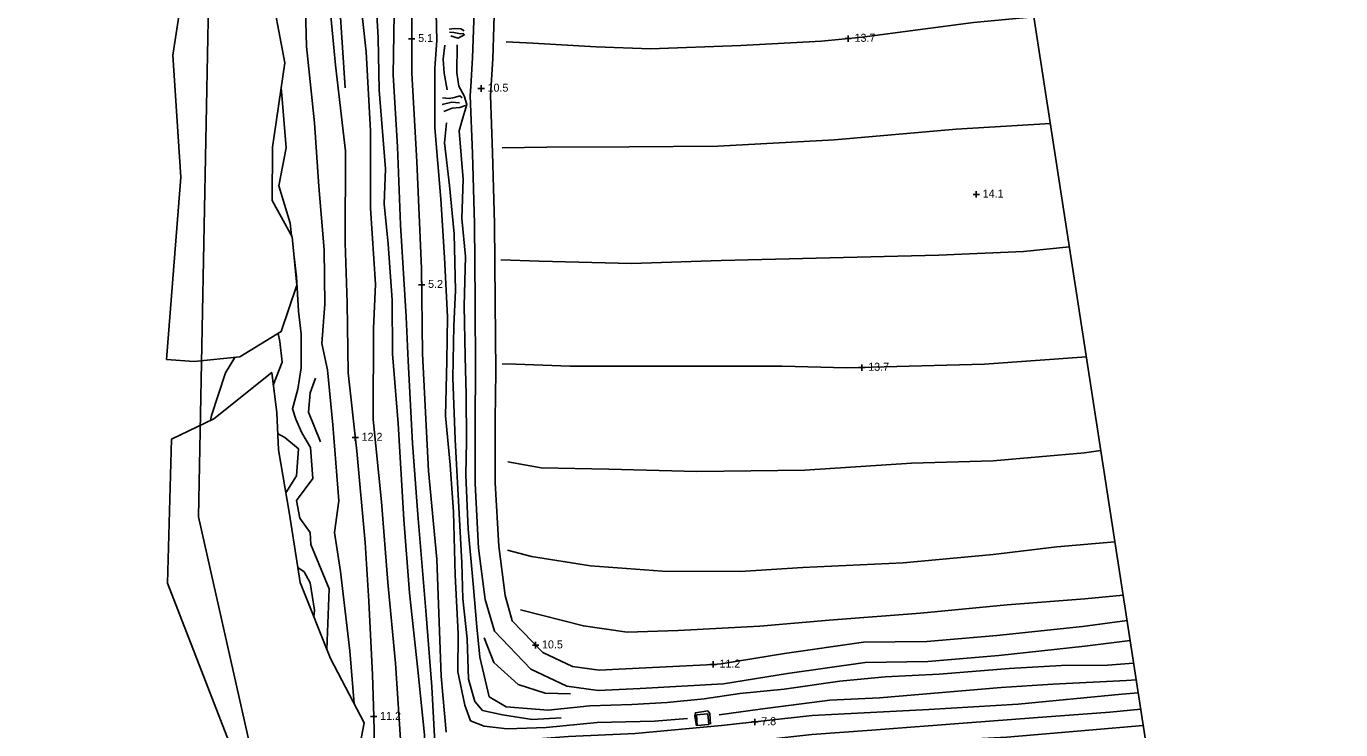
# Model space of a CAD drawing. Extents: x 2316231 to 2323598, y 363169 to 371906.
# Drawn here: x 2321107 to 2321928, y 367333 to 367772 of the extents above; entities that cross this region are included whole.
import ezdxf

# ---------------------------------------------------------------- set-up
doc = ezdxf.new("R2010")
doc.units = 0
for name, color, linetype in [('RD_DTM_BkLn1', 7, 'Continuous'), ('RD_DTM_Holes', 7, 'Continuous'), ('RD_DTM_TinHull', 7, 'Continuous'), ('RD_DTM_Void', 7, 'Continuous'), ('RD_EX_H2O', 7, 'Continuous'), ('RD_EX_Road', 7, 'Continuous')]:
    doc.layers.add(name, color=color, linetype=linetype)

msp = doc.modelspace()

# ---------------------------------------------------------------- linework, layer by layer
at = {"layer": 'RD_DTM_BkLn1'}
for points in [[(2321291.556, 368211.321), (2321295.001, 368190.387), (2321298.08, 368166.803), (2321301.743, 368125.311), (2321305.469, 368082.359), (2321306.836, 368033.666), (2321306.702, 368002.425), (2321307.621, 367978.771), (2321309.118, 367958.662), (2321310.087, 367912.89), (2321311.539, 367868.753), (2321315.416, 367819.072), (2321315.07, 367794.132), (2321319.37, 367756.054), (2321322.027, 367706.795), (2321322.055, 367658.395), (2321325.126, 367611.033), (2321323.802, 367583.298), (2321323.769, 367526.402), (2321328.977, 367475.147), (2321332.861, 367424.707), (2321337.695, 367374.238), (2321340.813, 367326.721), (2321341.673, 367288.712)], [(2321323.848, 368178.354), (2321329.394, 368134.038), (2321333.82, 368091.189), (2321336.523, 368053.927), (2321337.729, 368006.137), (2321339.028, 367970.354), (2321339.901, 367946.949), (2321338.401, 367905.143), (2321338.559, 367856.742), (2321336.201, 367820.434), (2321336.689, 367779.863), (2321336.124, 367741.67), (2321338.889, 367696.778), (2321340.671, 367647.964), (2321344.229, 367590.513), (2321345.519, 367563.202), (2321348.173, 367511.499), (2321351.642, 367467.184), (2321356.657, 367407.103), (2321360.332, 367359.488), (2321362.527, 367316.908)], [(2321259.144, 368129.166), (2321263.416, 368100.568), (2321268.448, 368072.192), (2321272.368, 368019.699), (2321273.45, 367993.54), (2321273.468, 367967.981), (2321272.707, 367951.314), (2321273.78, 367931.729), (2321274.21, 367887.23), (2321276.344, 367858.183), (2321280.683, 367806.494), (2321282.119, 367759.355), (2321287.064, 367711.792), (2321289.823, 367671.954), (2321293.058, 367632.446), (2321293.527, 367598.603), (2321291.556, 367573.993), (2321295.08, 367557.574), (2321298.476, 367523.214), (2321302.318, 367475.658), (2321299.498, 367455.835), (2321303.343, 367431.452), (2321309.119, 367381.926), (2321311.835, 367348.854)], [(2321296.973, 367943.164), (2321297.8, 367891.448), (2321301.079, 367812.439), (2321306.211, 367733.573)], [(2321324.018, 367340.884), (2321323.284, 367367.095), (2321320.999, 367412.97), (2321318.613, 367449.625), (2321313.402, 367506.623), (2321308.015, 367555.695), (2321307.438, 367599.364), (2321306.16, 367636.808), (2321306.457, 367694.13), (2321300.17, 367747.788), (2321294.617, 367807.101)], [(2321362.509, 367798.164), (2321363.504, 367763.154), (2321362.205, 367745.802), (2321362.227, 367708.722), (2321365.919, 367664.049), (2321368.33, 367627.608), (2321370.181, 367590.659), (2321369.724, 367563.062), (2321368.766, 367528.846), (2321371.721, 367498.156), (2321373.817, 367468.776), (2321374.916, 367429.162), (2321376.864, 367392.723), (2321376.536, 367368.934), (2321380.96, 367348.143), (2321384.558, 367338.381), (2321392.928, 367334.986), (2321407.453, 367333.24)], [(2321325.756, 367783.047), (2321326.872, 367764.755), (2321327.335, 367732.122), (2321331.382, 367683.033), (2321330.602, 367661.134), (2321332.959, 367635.929), (2321335.558, 367601.147), (2321335.671, 367567.436), (2321339.382, 367523.998), (2321342.772, 367463.961), (2321346.41, 367418.126), (2321351.625, 367370.075), (2321355.65, 367329.59), (2321356.833, 367292.277), (2321358.89, 367254.128), (2321360.361, 367211.012)], [(2321406.786, 367762.381), (2321423.381, 367761.454), (2321462.976, 367759.243), (2321496.869, 367757.943), (2321553.314, 367760.001), (2321603.808, 367762.852), (2321629.095, 367765.15), (2321698.646, 367774.31), (2321736.399, 367777.877)], [(2321371.234, 367770.288), (2321374.416, 367770.602), (2321378.403, 367770.532), (2321380.602, 367769.178)], [(2321371.342, 367768.425), (2321374.047, 367768.219), (2321378.147, 367767.377), (2321380.331, 367767.471)], [(2321372.207, 367766.058), (2321374.623, 367765.249), (2321376.861, 367764.608), (2321380.98, 367766.85)], [(2321368.507, 367760.289), (2321367.376, 367751.575), (2321367.978, 367742.791), (2321369.982, 367732.325)], [(2321376.161, 367760.518), (2321375.858, 367742.982), (2321377.21, 367734.668), (2321380.568, 367728.514), (2321382.246, 367723.212), (2321379.635, 367714.969), (2321377.368, 367706.759), (2321379.957, 367676.391), (2321378.961, 367651.906), (2321381.327, 367628.244), (2321380.484, 367597.434), (2321381.131, 367565.772), (2321381.716, 367541.883), (2321381.928, 367512.917), (2321381.496, 367491.716), (2321382.927, 367458.044), (2321386.063, 367423.912), (2321388.422, 367396.951), (2321390.234, 367377.944), (2321396.107, 367353.276), (2321406.762, 367347.08), (2321432.95, 367344.994), (2321458.986, 367347.62), (2321485.31, 367348.57), (2321507.328, 367349.76), (2321530.372, 367351.952), (2321552.7, 367355.406), (2321580.362, 367358.069), (2321615.205, 367363.029), (2321643.391, 367365.761), (2321677.301, 367367.403), (2321720.928, 367370.947), (2321753.64, 367372.763), (2321782.333, 367373.047), (2321798.692, 367374.245)], [(2321272.722, 367641.237), (2321271.772, 367648.992), (2321264.753, 367672.373), (2321269.257, 367696.042), (2321266.472, 367731.478), (2321266.154, 367733.618)], [(2321366.796, 367723.16), (2321372.856, 367724.572), (2321375.158, 367724.547), (2321377.612, 367724.236)], [(2321366.927, 367727.276), (2321371.102, 367726.991), (2321374.38, 367727.506), (2321377.827, 367728.578), (2321379.28, 367727.383)], [(2321367.72, 367718.835), (2321373, 367720.822), (2321377.856, 367721.351), (2321381.245, 367722.589)], [(2321369.4, 367711.706), (2321368.26, 367699.325), (2321371.32, 367672.514), (2321374.326, 367642.441), (2321375.116, 367606.957), (2321374.016, 367584.905), (2321373.412, 367552.527), (2321374.838, 367513.884), (2321377.035, 367475.414), (2321379.09, 367436.874), (2321379.755, 367414.515), (2321382.315, 367389.499), (2321383.285, 367364.338), (2321387.096, 367350.433), (2321391.893, 367344.793), (2321404.502, 367341.979), (2321422.996, 367339.107), (2321441.085, 367340.189)], [(2321404.218, 367696.102), (2321432.14, 367696.45), (2321483.414, 367696.77), (2321538.901, 367697.196), (2321611.886, 367701.127), (2321687.854, 367707.842), (2321746.664, 367711.361)], [(2321403.326, 367626.111), (2321427.421, 367625.449), (2321485.056, 367623.952), (2321541.026, 367625.763), (2321600.387, 367627.306), (2321677.062, 367629.021), (2321729.937, 367631.336), (2321758.557, 367634.303)], [(2321294.757, 367382.852), (2321296.138, 367420.72), (2321284.824, 367448.456), (2321284.286, 367455.876), (2321277.799, 367464.765), (2321275.752, 367475.848), (2321285.906, 367489.672), (2321284.594, 367508.961), (2321279.094, 367518.106), (2321275.466, 367526.765), (2321273.189, 367533.222), (2321276.665, 367545.352), (2321278.712, 367558.736), (2321278.622, 367580.072), (2321276.971, 367594.047), (2321275.873, 367615.507), (2321274.344, 367627.995)], [(2321261.282, 367547.974), (2321266.736, 367562.188), (2321265.293, 367575.284), (2321264.3, 367580.211)], [(2321237.271, 367565.251), (2321231.527, 367555.545), (2321222.771, 367528.969), (2321222.101, 367525.922)], [(2321404.325, 367561.164), (2321412.868, 367560.996), (2321446.583, 367559.756), (2321517.126, 367559.869), (2321579.088, 367559.723), (2321619.342, 367558.636), (2321705.596, 367560.971), (2321769.169, 367565.539)], [(2321287.669, 367552.253), (2321284.234, 367543.16), (2321283.239, 367531.087), (2321290.773, 367512.509)], [(2321269.146, 367480.568), (2321275.829, 367491.225), (2321276.983, 367508.198), (2321268.398, 367515.19), (2321263.988, 367517.677)], [(2321407.839, 367500.083), (2321428.618, 367496.296), (2321470.808, 367495.446), (2321525.904, 367494.046), (2321593.33, 367494.842), (2321659.91, 367499.143), (2321710.989, 367500.686), (2321767.962, 367505.695), (2321778.197, 367507.044)], [(2321407.626, 367444.884), (2321422.542, 367440.847), (2321459.458, 367435.115), (2321504.339, 367431.722), (2321552.845, 367431.536), (2321592.064, 367434.013), (2321654.827, 367436.972), (2321710.911, 367442.247), (2321750.736, 367446.964), (2321786.995, 367450.033)], [(2321286.694, 367403.07), (2321287.065, 367407.293), (2321284.33, 367424.55), (2321280.583, 367431.252), (2321276.633, 367433.945)], [(2321415.716, 367407.686), (2321454.981, 367397.55), (2321482.38, 367393.737), (2321514.21, 367394.667), (2321565.213, 367397.445), (2321608.426, 367401.181), (2321665.632, 367405.465), (2321719.628, 367410.812), (2321768.157, 367414.517), (2321792.139, 367416.706)], [(2321393.093, 367390.018), (2321398.96, 367374.63), (2321414.33, 367360.978), (2321431.1, 367355.565), (2321446.963, 367355.2)], [(2321539.753, 367342.119), (2321565.41, 367345.578), (2321608.978, 367351.187), (2321639.898, 367352.729), (2321715.9, 367359.182), (2321748.187, 367361.273), (2321794.143, 367363.415), (2321800.287, 367363.908)], [(2321383.243, 367297.551), (2321386.5, 367309.013), (2321395.766, 367314.976), (2321434.231, 367320.424), (2321475.646, 367323.151), (2321511.83, 367324.08), (2321529.119, 367324.075), (2321562.377, 367325.792), (2321597.747, 367329.681), (2321635.223, 367332.441), (2321694.923, 367337.008), (2321736.08, 367340.151), (2321783.86, 367343.789), (2321803.103, 367345.663)], [(2321534.458, 367336.206), (2321534.045, 367342.794), (2321532.69, 367344.451), (2321524.935, 367343.321), (2321524.568, 367341.413), (2321525.357, 367336.271), (2321525.54, 367335.178)], [(2321328.403, 367278.384), (2321324.798, 367313.014), (2321324.018, 367340.884)], [(2321407.453, 367333.24), (2321431.819, 367334.143), (2321463.577, 367337.187), (2321499.322, 367338.071), (2321520.058, 367339.744)], [(2321415.257, 367297.46), (2321430.604, 367306.835), (2321453.602, 367309.277), (2321487.438, 367310.338), (2321506.208, 367308.082), (2321516.399, 367305.792), (2321525.885, 367304.622), (2321530.952, 367310.691), (2321539.181, 367313.918), (2321563.501, 367315.142), (2321593.054, 367316.252), (2321642.292, 367321.567), (2321684.276, 367326.295), (2321719.575, 367328.025), (2321770.707, 367332.534), (2321804.686, 367335.402)]]:
    msp.add_lwpolyline(points, dxfattribs=at)
at = {"layer": 'RD_DTM_Holes'}
for points in [[(2321194.626, 367563.982), (2321211.931, 367562.731), (2321240.449, 367565.568), (2321266.278, 367581.425), (2321276.069, 367610.309), (2321273.123, 367640.512), (2321260.57, 367663.201), (2321260.823, 367696.519), (2321268.403, 367749.265), (2321258.641, 367801.152), (2321254.344, 367804.974), (2321247.579, 367829.207), (2321239.086, 367854.281), (2321227.889, 367865.18), (2321214.697, 367859.513), (2321198.6, 367753.989), (2321203.438, 367677.795), (2321194.626, 367563.982)], [(2321305.88, 367273.604), (2321317.984, 367337.094), (2321297.001, 367377.227), (2321278.065, 367424.705), (2321271.443, 367467.424), (2321264.449, 367507.44), (2321263.408, 367530.561), (2321260.327, 367555.794), (2321224.183, 367526.92), (2321197.743, 367514.235), (2321195.168, 367424.201), (2321257.373, 367263.844), (2321272.724, 367127.144), (2321274.192, 366988.754), (2321266.646, 366868.055), (2321260.533, 366796.556)]]:
    msp.add_lwpolyline(points, dxfattribs=at)
at = {"layer": 'RD_DTM_TinHull'}
for points in [[(2322749.057, 368805.183), (2322437.788, 368637.943), (2322185.484, 368501.144), (2321988.712, 368397.613), (2321906.574, 368261.806), (2321814.258, 368125.896), (2321753.197, 367969.571), (2321734.081, 367792.897), (2321812.341, 367285.803), (2321826.603, 366879.552), (2321787.983, 366568.052), (2321665.825, 366287.064), (2321428.475, 366067.062), (2321222.139, 365846.682), (2320971.939, 365770.635), (2320807.161, 365571.8), (2320809.363, 365353.877), (2320991.706, 364942.038)], [(2318009.783, 367630.234), (2318999.407, 367049.655), (2319281.252, 367000.442), (2319521.217, 366961.394), (2320716.689, 366226.888), (2320934.852, 366280.749), (2321141.465, 366502.562), (2321263.978, 366719.924), (2321282.537, 366948.249), (2321279.947, 367175.232), (2321214.652, 367465.641), (2321221.515, 367818.629), (2321207.427, 368150.673), (2321267.86, 368369.229), (2321400.963, 368599.408), (2321534.916, 368777.939)]]:
    msp.add_lwpolyline(points, dxfattribs=at)
at = {"layer": 'RD_DTM_Void'}
for p, q in [((2321345.775, 367764.221), (2321349.775, 367764.221)), ((2321347.775, 367762.221), (2321347.775, 367766.221)), ((2321618.349, 367764.355), (2321622.349, 367764.355)), ((2321620.349, 367762.355), (2321620.349, 367766.355)), ((2321389.132, 367733.199), (2321393.132, 367733.199)), ((2321391.132, 367731.199), (2321391.132, 367735.199)), ((2321698.397, 367667.057), (2321702.397, 367667.057)), ((2321700.397, 367665.057), (2321700.397, 367669.057)), ((2321351.982, 367610.638), (2321355.982, 367610.638)), ((2321353.982, 367608.638), (2321353.982, 367612.638)), ((2321626.889, 367558.894), (2321630.889, 367558.894)), ((2321628.889, 367556.894), (2321628.889, 367560.894)), ((2321312.465, 367513.161), (2321312.465, 367517.161)), ((2321310.465, 367515.161), (2321314.465, 367515.161)), ((2321423.148, 367385.515), (2321427.148, 367385.515)), ((2321425.148, 367383.515), (2321425.148, 367387.515)), ((2321534.008, 367373.538), (2321538.008, 367373.538)), ((2321536.008, 367371.538), (2321536.008, 367375.538)), ((2321322.018, 367340.884), (2321326.018, 367340.884)), ((2321324.018, 367338.884), (2321324.018, 367342.884)), ((2321560.075, 367337.551), (2321564.075, 367337.551)), ((2321562.075, 367335.551), (2321562.075, 367339.551))]:
    msp.add_line(p, q, dxfattribs=at)
at = {"layer": 'RD_EX_H2O'}
for points in [[(2321369.329, 367331.29), (2321366.09, 367366.171), (2321363.488, 367439.267), (2321358.267, 367494.497), (2321354.538, 367567.493), (2321353.85, 367620.821), (2321350.939, 367687.536), (2321347.746, 367742.694), (2321347.799, 367782.539), (2321347.874, 367844.466), (2321349.179, 367907.798), (2321351.639, 367957.667), (2321344.793, 367998.573), (2321347.089, 368028.366), (2321348.65, 368062.186), (2321346.173, 368103.66), (2321341.01, 368148.317), (2321343.787, 368191.312)], [(2321801.546, 367355.747), (2321791.305, 367354.864), (2321726.612, 367348.618), (2321670.729, 367345.347), (2321597.982, 367341.509), (2321541.334, 367335.264), (2321487.317, 367330.345), (2321445.669, 367328.545), (2321421.333, 367326.586), (2321395.38, 367326.144), (2321370.092, 367323.418)]]:
    msp.add_lwpolyline(points, dxfattribs=at)
at = {"layer": 'RD_EX_Road'}
for points in [[(2321432.02, 368218.121), (2321417.465, 368191.942), (2321405.484, 368161.595), (2321398.304, 368132.626), (2321394.002, 368104.377), (2321392.82, 368087.066), (2321390.795, 368062.086), (2321390.92, 368033.93), (2321391.721, 368005.538), (2321393.319, 367971.862), (2321394.062, 367949.513), (2321391.333, 367918.744), (2321389.073, 367880.971), (2321388.153, 367831.01), (2321387.175, 367793.2), (2321385.791, 367752.377), (2321384.658, 367734.528)], [(2321399.722, 367792.825), (2321398.329, 367751.767), (2321396.868, 367728.73), (2321398.202, 367692.941), (2321399.492, 367648.912), (2321399.84, 367600.23), (2321400.203, 367556.35), (2321399.864, 367526.574), (2321399.964, 367486.837), (2321402.073, 367447.338), (2321406.048, 367416.512), (2321410.572, 367400.685), (2321429.628, 367380.852), (2321448.225, 367372.168), (2321464.833, 367369.833), (2321489.792, 367371.066), (2321536.008, 367373.538)], [(2321384.658, 367734.528), (2321384.301, 367728.894), (2321385.657, 367692.524), (2321386.942, 367648.684), (2321387.288, 367600.133), (2321387.651, 367556.369), (2321387.312, 367526.63), (2321387.413, 367486.486), (2321389.564, 367446.199), (2321393.72, 367413.97), (2321399.36, 367394.237), (2321422.198, 367370.469), (2321444.617, 367360), (2321464.264, 367357.237), (2321490.437, 367358.531), (2321542.433, 367361.312), (2321582.556, 367367.853), (2321631.001, 367374.789), (2321670.123, 367375.342), (2321714.502, 367379.11), (2321768.115, 367384.83), (2321796.493, 367388.492)], [(2321536.008, 367373.538), (2321541.084, 367373.809), (2321580.656, 367380.261), (2321630.019, 367387.329), (2321669.502, 367387.886), (2321713.305, 367391.605), (2321766.645, 367397.296), (2321794.578, 367400.901)], [(2321525.699, 367341.976), (2321532.726, 367342.552), (2321533.246, 367335.928), (2321526.135, 367335.4), (2321525.699, 367341.976)]]:
    msp.add_lwpolyline(points, dxfattribs=at)

# ---------------------------------------------------------------- texts
at = {"layer": 'RD_DTM_Void'}
for s, p in [('5.1', (2321351.775, 367762.221)), ('13.7', (2321624.349, 367762.355)), ('10.5', (2321395.132, 367731.199)), ('14.1', (2321704.397, 367665.057)), ('5.2', (2321357.982, 367608.638)), ('13.7', (2321632.889, 367556.894)), ('12.2', (2321316.465, 367513.161)), ('10.5', (2321429.148, 367383.515)), ('11.2', (2321540.008, 367371.538)), ('11.2', (2321328.018, 367338.884)), ('7.8', (2321566.075, 367335.551))]:
    msp.add_text(s, height=5, dxfattribs=at).set_placement(p)

doc.saveas('drawing.dxf')
